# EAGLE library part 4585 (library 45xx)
4-bit COMPARATOR (MC14585BCP)
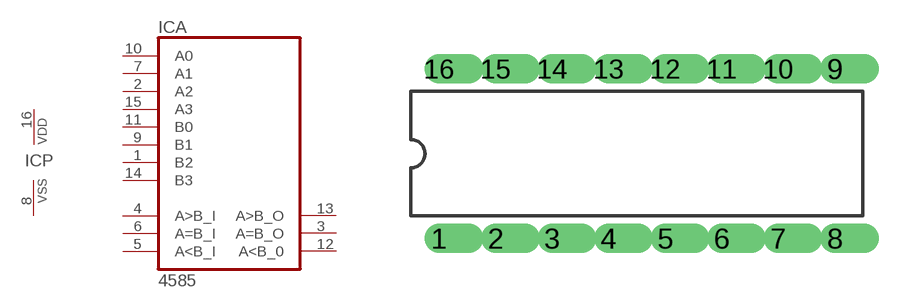
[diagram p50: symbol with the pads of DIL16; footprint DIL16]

Designator prefix IC; gates A=4585 P=PWRN

## 4585N  [DIL16]
1  A:B2  in
2  A:A2  in
3  A:A=B_O  out
4  A:A>B_I  in
5  A:A<B_I  in
6  A:A=B_I  in
7  A:A1  in
8  P:VSS  pwr
9  A:B1  in
10  A:A0  in
11  A:B0  in
12  A:A<B_0  out
13  A:A>B_O  out
14  A:B3  in
15  A:A3  in
16  P:VDD  pwr

## Footprint DIL16 (pad centres in mm)
Dual In Line
drill 0.813 offset: 1 -8.89,-3.81; 2 -6.35,-3.81; 3 -3.81,-3.81; 4 -1.27,-3.81; 5 1.27,-3.81; 6 3.81,-3.81; 7 6.35,-3.81; 8 8.89,-3.81; 9 8.89,3.81; 10 6.35,3.81; 11 3.81,3.81; 12 1.27,3.81; 13 -1.27,3.81; 14 -3.81,3.81; 15 -6.35,3.81; 16 -8.89,3.81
